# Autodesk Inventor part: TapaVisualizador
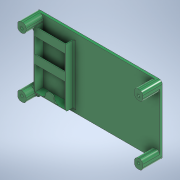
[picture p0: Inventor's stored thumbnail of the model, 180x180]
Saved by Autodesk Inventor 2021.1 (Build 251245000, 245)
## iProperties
Created: 2021-06
Part Number: TapaVisualizador
Material: Genérico
Document SubType Name: Modeling
Designer: Ricardo
Density: 1 g/cm^3
Appearance: Valor por defecto
Author: Ricardo
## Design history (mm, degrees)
sketch "Boceto1"
  geometry: L1 (-71, 41.5)-(71, 41.5); L2 (-75, -37.5)-(-75, 37.5); L3 (71, -41.5)-(-71, -41.5); L4 (75, 37.5)-(75, -37.5); L5 (-70, -35)-(70, -35); L6 (70, -35)-(70, 35); L7 (70, 35)-(-70, 35); L8 (-70, 35)-(-70, -35); L9 (-70, -35)-(70, 35); L10 (70, -35)-(-70, 35); L11 (-65, 35)-(-65, 41.5); L12 (-70, 30)-(-75, 30); L13 (0, -59.26)-(0, 59.26) reference; L14 (-106.16, 0)-(106.16, 0) reference; L15 (65, 35)-(65, 41.5); L16 (70, 30)-(75, 30); L17 (-70, -30)-(-75, -30); L18 (-65, -35)-(-65, -41.5); L19 (65, -35)-(65, -41.5); L20 (70, -30)-(75, -30); C1 r 1.7 at (70, -35); C2 r 1.7 at (70, 35); C3 r 1.7 at (-70, 35); C4 r 1.7 at (-70, -35); A1 r 4 centre (-71, 37.5) between (-71, 41.5) and (-75, 37.5); A2 r 4 centre (-71, -37.5) between (-75, -37.5) and (-71, -41.5); A3 r 4 centre (71, -37.5) between (71, -41.5) and (75, -37.5); A4 r 4 centre (71, 37.5) between (75, 37.5) and (71, 41.5); A5 r 5 centre (-70, 35) between (-70, 30) and (-65, 35); A6 r 5 centre (70, 35) between (65, 35) and (70, 30); A7 r 5 centre (-70, -35) between (-65, -35) and (-70, -30); A8 r 5 centre (70, -35) between (70, -30) and (65, -35); 8 further points
  constraints: 36 end point, 16 point on circle, 15 symmetric about line, 12 centre point, 4 point on line, 3 perpendicular, 3 tangent, 2 midpoint, 2 parallel, 1 horizontal, 3 other
  dimensions: "d0" = 150 distance between parallel lines of L4 L2; "d1" = 83 distance between parallel lines of L3 L1; "d2" = 140 distance of L6.end L7.end; "d3" = 70 distance of L5.end L6.end; "d4" = 3.4 diameter of C2 (= d5); "d5" = 3.4 diameter of C3; "d6" = 3.4 diameter of C4 (= d5); "d7" = 3.4 diameter of C1 (= d5)
extrude "Extrusión1" new body sketch "Boceto1" distance "d8" = 3; taper "d9" = 0 deg
extrude "Extrusión2" join sketch "Boceto1" distance "d10" = 20.5; taper "d11" = 0 deg
sketch "Boceto2"
  geometry: L1 (-70, 35)-(-57.574, 35); L2 (-57.574, 35)-(-57.574, 26.868); C1 r 1.7 at (-70, 35) reference; C2 r 4 at (-57.574, 26.868); 1 further point
  constraints: 4 end point, 1 centre point, 1 coincident, 1 horizontal, 1 perpendicular
  dimensions: "d12" = 12.426 distance of L1.start L1.end; "d13" = 8.132 distance of L1.end L2.end; "d14" = 8 diameter of C2
extrude "Extrusión3" cut sketch "Boceto2" extent not by distance; stored distance "d15" = 0; taper "d16" = 0 deg
sketch "Boceto3"
  geometry: L1 (-65, 35)-(-65, 41.5) reference; L2 (-65, -41.5)-(-65, -35) reference; L3 (-65, 35)-(-65, -34); L4 (-66.2, -41.5)-(-66.2, -35); L5 (-66.2, -35)-(-66.2, 35); L6 (-66.2, 35)-(-66.2, 41.5); L7 (-29, -41.5)-(-29, -36); L8 (-29, -34)-(-29, 35); L9 (-29, 35)-(-29, 41.5); L10 (-27.8, 41.5)-(-27.8, 35); L11 (-27.8, 35)-(-27.8, -35); L12 (-27.8, -35)-(-27.8, -41.5); L13 (-105, 0)-(105, 0) reference; L14 (-65, 0)-(-29, 0); L15 (-65, -34)-(-29, -34); L16 (-66.2, 34)-(-27.8, 34); L17 (-66.2, -36)-(-27.8, -36); 3 further points
  constraints: 28 end point, 9 point on line, 4 collinear, 3 parallel
  dimensions: "d17" = 1.2 distance between parallel lines of L3 L5; "d18" = 36 distance between parallel lines of L3 L8; "d19" = 1.2 distance between parallel lines of L8 L11; "d20" = 34 distance between parallel lines of L14 L15; "d21" = 34 distance between parallel lines of L14 L16; "d22" = 2 distance between parallel lines of L15 L17
extrude "Extrusión4" join sketch "Boceto3" distance "d23" = 9; taper "d24" = 0 deg
sketch "Boceto4"
  geometry: L1 (-66.2, 31.75)-(-66.2, -31.75) reference; L2 (-27.8, -36)-(-65, -36) reference; L3 (-65, -36)-(-65, -41.5) reference; L4 (-65, -41.5)-(65, -41.5) reference; L5 (65, -41.5)-(65, -35) reference; L6 (70, -30)-(75, -30) reference; L7 (75, -30)-(75, 30) reference; L8 (75, 30)-(70, 30) reference; L9 (65, 35)-(65, 41.5) reference; L10 (65, 41.5)-(-65, 41.5) reference; L11 (-65, 41.5)-(-65, 35) reference; L12 (-65.101, 34)-(-65, 34) reference; L13 (-65, 34)-(-65, -34) reference; L14 (-65, -34)-(-29, -34) reference; L15 (-29, -34)-(-29, 34) reference; L16 (-29, 34)-(-27.8, 34) reference; L17 (-27.8, 34)-(-27.8, -36) reference; L18 (-65, -36)-(-27.8, -36) reference; L19 (-27.8, 34)-(-66.2, 34); L20 (-66.2, 34)-(-66.2, 31.75); L21 (-66.2, -31.75)-(-66.2, 31.75) reference; L22 (-66.2, 24)-(-27.8, 24); L23 (-27.8, -26)-(-66.2, -26); L24 (-66.2, 0)-(-27.8, 0); L25 (-66.2, 5)-(-27.8, 5); L26 (-66.2, -5)-(-27.8, -5); L27 (-66.2, -26)-(-66.2, -36); L28 (-27.8, -36)-(-65, -36) reference; L29 (-66.2, -36)-(-27.8, -36); L30 (-27.8, -36)-(-27.8, -26); L31 (-47, -36)-(-47, 34); L32 (-50, -36)-(-50, 34); L33 (-44, -36)-(-44, 34); C1 r 4 at (57.574, 26.868) reference; A1 r 5 centre (70, -35) between (70, -30) and (65, -35) reference; A2 r 5 centre (70, 35) between (65, 35) and (70, 30) reference; A3 r 5 centre (-70, 35) between (-65.101, 34) and (-65, 35) reference; A4 r 5 centre (-70, 35) between (-66.2, 31.75) and (-65.101, 34) reference; 22 further points
  constraints: 26 end point, 5 parallel, 5 point on line, 3 midpoint, 3 perpendicular, 2 collinear, 1 horizontal
  dimensions: "d25" = 10 distance between parallel lines of L22 L19; "d26" = 10 distance between parallel lines of L2 L23; "d27" = 5 distance between parallel lines of L24 L25; "d28" = 5 distance between parallel lines of L24 L26; "d33" = 3 distance between parallel lines of L31 L32; "d34" = 3 distance between parallel lines of L31 L33
extrude "Extrusión5" join sketch "Boceto4" distance "d29" = 1; taper "d30" = 0 deg
fillet "Empalme1" dims "d31" = 2
fillet "Empalme2" dims "d32" = 4
sketch "Boceto5"
  geometry: L1 (-75, 41.5)-(75, 41.5); L2 (75, 41.5)-(75, -41.5); L3 (75, -41.5)-(-75, -41.5); L4 (-75, -41.5)-(-75, 41.5); L5 (-75, 37.5)-(-75, 41.5); L6 (-75, 41.5)-(-71, 41.5); L7 (75, -37.5)-(75, -41.5); L8 (-71, -41.5)-(71, -41.5) reference; L9 (75, -41.5)-(71, -41.5); A1 r 4 centre (-71, 37.5) between (-71, 41.5) and (-75, 37.5) reference; A2 r 4 centre (71, -37.5) between (71, -41.5) and (75, -37.5) reference; 4 further points
  constraints: 8 end point, 4 coincident, 3 tangent, 2 vertical, 1 collinear, 1 perpendicular, 1 point on circle, 2 other
extrude "Extrusión6" cut sketch "Boceto5" distance "d36" = 2; taper "d37" = 0 deg
sketch "Boceto6"
  geometry: C1 r 1.7 at (-70, 35) reference; C2 r 1.7 at (-70, -35) reference; C3 r 1.7 at (70, -35) reference; C4 r 1.7 at (70, 35) reference; C5 r 2.6 at (-70, 35); C6 r 2.6 at (70, 35); C7 r 2.6 at (70, -35); C8 r 2.6 at (-70, -35); A1 r 5 centre (-70, 35) between (-70, 30) and (-65, 35) reference; 1 further point
  constraints: 4 centre point, 4 coincident
  dimensions: "d38" = 5.2 diameter of C5; "d39" = 5.2 diameter of C6; "d40" = 5.2 diameter of C7; "d41" = 5.2 diameter of C8
extrude "Extrusión7" cut sketch "Boceto6" distance "d42" = 2; taper "d43" = 0 deg
sketch "Boceto7"
  geometry: L1 (-29, 34)-(-25.8, 34) reference; L2 (-25.8, -38)-(-25.8, 34) reference; L3 (-65, -38)-(-25.8, -38) reference; L4 (-65, -38)-(-65, -41.5) reference; L5 (-65, -41.5)-(69, -41.5) reference; L6 (65, -37.5)-(65, -35) reference; L7 (70, -30)-(71, -30) reference; L8 (75, -34)-(75, 34) reference; L9 (71, 30)-(70, 30) reference; L10 (65, 35)-(65, 37.5) reference; L11 (69, 41.5)-(-69, 41.5) reference; L12 (-65, 37.5)-(-65, 35) reference; L13 (-65.101, 34)-(-65, 34) reference; L14 (-65, 34)-(-65, -34) reference; L15 (-65, -34)-(-29, -34) reference; L16 (-29, -34)-(-29, 34) reference; L17 (-29, -26)-(-65, -26) reference; L18 (-29, -26)-(-65, -26) reference; L19 (-47, -26)-(-47, -34); L20 (-42, -26)-(-42, -34); L21 (-52, -26)-(-52, -34); L22 (-27.8, -34)-(-63, -34) reference; L23 (-27.8, -34)-(-27.8, -26) reference; L24 (-27.8, -26)-(-29, -26) reference; L25 (-29, -26)-(-65, -26) reference; L26 (-65, -26)-(-66.2, -26) reference; L27 (-66.2, -26)-(-66.2, -28.235) reference; C1 r 4 at (57.574, 26.868) reference; A1 r 4 centre (69, -37.5) between (65, -37.5) and (69, -41.5) reference; A2 r 5 centre (70, -35) between (70, -30) and (65, -35) reference; A3 r 4 centre (71, -34) between (75, -34) and (71, -30) reference; A4 r 4 centre (71, 34) between (71, 30) and (75, 34) reference; A5 r 5 centre (70, 35) between (65, 35) and (70, 30) reference; A6 r 4 centre (69, 37.5) between (69, 41.5) and (65, 37.5) reference; A7 r 4 centre (-69, 37.5) between (-65, 37.5) and (-69, 41.5) reference; A8 r 5 centre (-70, 35) between (-65.101, 34) and (-65, 35) reference; A9 r 4 centre (-63, -38) between (-63, -34) and (-65.02, -34.548) reference; A10 r 2 centre (-68.2, -28.235) between (-68.714, -30.168) and (-66.2, -28.235) reference; A11 r 5 centre (-70, -35) between (-65.02, -34.548) and (-68.714, -30.168) reference; 5 further points
  constraints: 6 end point, 2 midpoint, 2 parallel
  dimensions: "d44" = 5 distance between parallel lines of L19 L20; "d45" = 5 distance between parallel lines of L19 L21
extrude "Extrusión8" cut sketch "Boceto7" stored distance "d46" = 10; taper "d47" = 0 deg
fillet "Empalme4" dims "d48" = 4
sketch "Boceto8"
  geometry: L1 (-27.8, 5)-(-29, 5) reference; L2 (-27.8, 5)-(-27.8, 6.732) reference; L3 (-29, 5)-(-29, 6.732) reference; L4 (-29, 22.268)-(-29, 6.732) reference; L5 (-27.8, 6.732)-(-27.8, 22.268) reference; L6 (-29, 24)-(-29, 22.268) reference; L7 (-27.8, 24)-(-27.8, 22.268) reference; L8 (-29, 24)-(-27.8, 24) reference; L9 (-66.2, 24)-(-65, 24) reference; L10 (-65, 24)-(-65, 22.268) reference; L11 (-66.2, 24)-(-66.2, 22.268) reference; L12 (-66.2, 22.268)-(-66.2, 6.732) reference; L13 (-65, 6.732)-(-65, 22.268) reference; L14 (-65, 5)-(-65, 6.732) reference; L15 (-65, 5)-(-66.2, 5) reference; L16 (-66.2, 5)-(-66.2, 6.732) reference; L17 (-29, 34)-(-25.8, 34) reference; L18 (-25.8, -38)-(-25.8, 34) reference; L19 (-65, -38)-(-25.8, -38) reference; L20 (-65, -38)-(-65, -41.5) reference; L21 (-65, -41.5)-(69, -41.5) reference; L22 (65, -37.5)-(65, -35) reference; L23 (70, -30)-(71, -30) reference; L24 (75, -34)-(75, 34) reference; L25 (71, 30)-(70, 30) reference; L26 (65, 35)-(65, 37.5) reference; L27 (69, 41.5)-(-69, 41.5) reference; L28 (-65, 37.5)-(-65, 35) reference; L29 (-65.101, 34)-(-65, 34) reference; L30 (-65, 34)-(-65, -34) reference; L31 (-65, -34)-(-29, -34) reference; L32 (-29, -34)-(-29, 34) reference; L33 (-66.2, -26)-(-66.2, -24.268) reference; L34 (-65, -26)-(-66.2, -26) reference; L35 (-66.2, -6.732)-(-66.2, -24.268) reference; L36 (-66.2, -5)-(-66.2, -6.732) reference; L37 (-66.2, -5)-(-65, -5) reference; L38 (-29, -5)-(-27.8, -5) reference; L39 (-27.8, -5)-(-27.8, -6.732) reference; L40 (-27.8, -24.268)-(-27.8, -6.732) reference; L41 (-27.8, -26)-(-27.8, -24.268) reference; L42 (-27.8, -26)-(-29, -26) reference; C1 r 4 at (57.574, 26.868) reference; A1 r 4 centre (69, -37.5) between (65, -37.5) and (69, -41.5) reference; A2 r 5 centre (70, -35) between (70, -30) and (65, -35) reference; A3 r 4 centre (71, -34) between (75, -34) and (71, -30) reference; A4 r 4 centre (71, 34) between (71, 30) and (75, 34) reference; A5 r 5 centre (70, 35) between (65, 35) and (70, 30) reference; A6 r 4 centre (69, 37.5) between (69, 41.5) and (65, 37.5) reference; A7 r 4 centre (-69, 37.5) between (-65, 37.5) and (-69, 41.5) reference; A8 r 5 centre (-70, 35) between (-65.101, 34) and (-65, 35) reference; 1 further point
extrude "Extrusión9" join sketch "Boceto8" stored distance "d49" = 10; taper "d50" = 0 deg
node "Sólido1"
node "Contorno proyectado1"
node "Contorno proyectado2"
node "Contorno proyectado3"
node "Contorno proyectado4"
